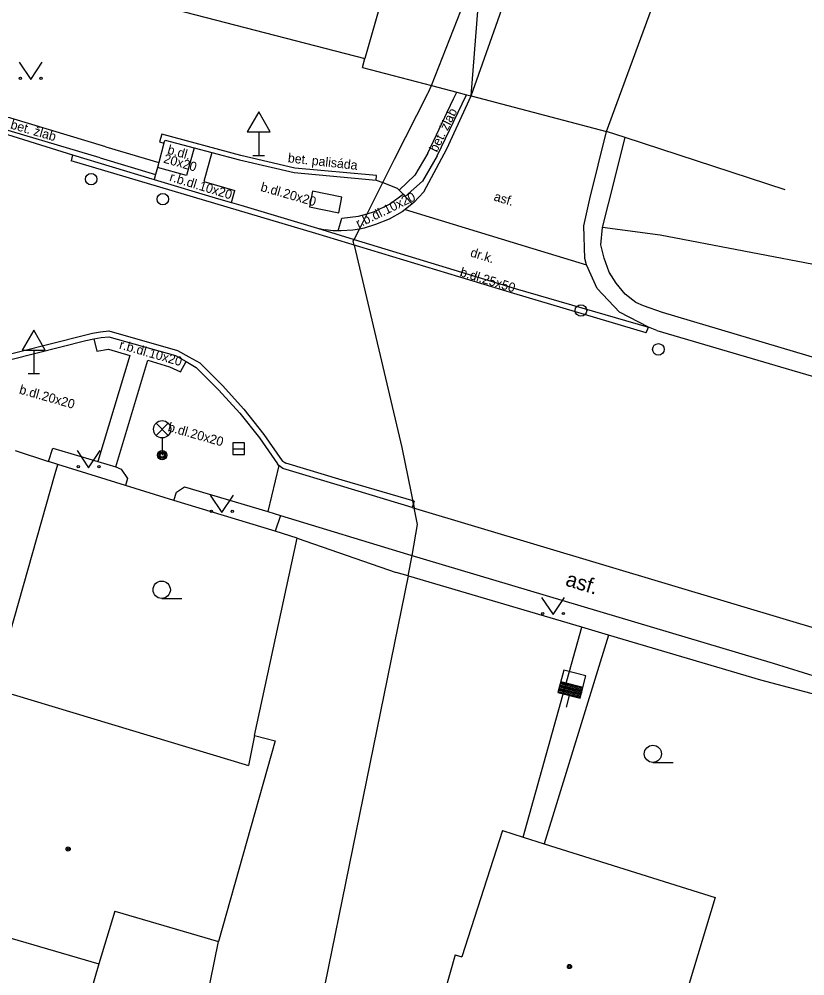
# Model space of a CAD drawing. Extents: x -599951 to -598963, y -1164095 to -1162939.
# Drawn here: x -599705.43 to -599671.33, y -1164061.65 to -1164020.14 of the extents above; entities that cross this region are included whole.
import ezdxf

# ---------------------------------------------------------------- set-up
doc = ezdxf.new("R2010")
doc.units = 0
for name, color, linetype in [('Level 1', 7, 'Continuous'), ('Level 10', 7, 'Continuous'), ('Level 11', 7, 'Continuous'), ('Level 14', 7, 'Continuous'), ('Level 26', 7, 'Continuous'), ('Level 27', 7, 'Continuous'), ('Level 28', 7, 'Continuous'), ('Level 33', 7, 'Continuous'), ('Level 34', 7, 'Continuous'), ('Level 36', 7, 'Continuous'), ('Level 39', 7, 'Continuous'), ('Level 40', 7, 'Continuous'), ('Level 42', 7, 'Continuous'), ('Level 5', 7, 'Continuous'), ('Level 7', 7, 'Continuous'), ('Level 8', 7, 'Continuous')]:
    doc.layers.add(name, color=color, linetype=linetype)

msp = doc.modelspace()

# ---------------------------------------------------------------- linework, layer by layer
at = {"layer": 'Level 1'}
for points in [[(-599689.65, -1164027.23), (-599689.14, -1164026.22), (-599687.7, -1164023.36), (-599687.67, -1164023.31), (-599687.53, -1164023.02), (-599685.47, -1164017.74), (-599684.35, -1164014.85), (-599680.77, -1164005.81)], [(-599689.65, -1164027.23), (-599689.14, -1164026.22), (-599687.7, -1164023.36), (-599687.67, -1164023.31), (-599687.53, -1164023.02), (-599685.47, -1164017.74), (-599684.35, -1164014.85), (-599680.77, -1164005.81)], [(-599690.33, -1164028.58), (-599689.65, -1164027.23)], [(-599690.66, -1164029.25), (-599690.33, -1164028.58)], [(-599690.66, -1164029.25), (-599690.33, -1164028.58)], [(-599690.89, -1164029.7), (-599690.66, -1164029.25)], [(-599690.89, -1164029.7), (-599690.66, -1164029.25)], [(-599690.89, -1164029.94), (-599690.93, -1164029.78), (-599690.89, -1164029.7)], [(-599690.89, -1164029.94), (-599690.93, -1164029.78), (-599690.89, -1164029.7)], [(-599690.89, -1164029.94), (-599688.82, -1164038.73), (-599688.29, -1164041.35)], [(-599690.89, -1164029.94), (-599688.82, -1164038.73), (-599688.29, -1164041.35)], [(-599688.32, -1164041.18), (-599688.35, -1164041.04)], [(-599688.54, -1164044.3), (-599688.37, -1164043.42), (-599688.14, -1164042.07), (-599688.29, -1164041.35)], [(-599688.54, -1164044.3), (-599688.37, -1164043.42), (-599688.14, -1164042.07), (-599688.29, -1164041.35)]]:
    msp.add_lwpolyline(points, dxfattribs=at)
at = {"layer": 'Level 10'}
for points in [[(-599679.94, -1164025.02), (-599673.88, -1164008.52), (-599673.11, -1164006.34)], [(-599737.46, -1164015.3), (-599717.42, -1164021.56), (-599703.11, -1164026.03)], [(-599686.87, -1164025.77), (-599685.82, -1164023.47)], [(-599680.67, -1164027.93), (-599679.94, -1164025.02)], [(-599703.11, -1164026.03), (-599699.67, -1164027.07), (-599699.57, -1164027.1), (-599696.78, -1164027.94), (-599696.21, -1164028.1), (-599695.81, -1164028.21), (-599692.48, -1164029.21)], [(-599687.86, -1164027.63), (-599686.87, -1164025.77)], [(-599687.86, -1164027.63), (-599688.3, -1164028.1), (-599688.37, -1164028.16), (-599688.67, -1164028.4), (-599688.81, -1164028.5), (-599689.37, -1164028.82), (-599689.97, -1164029.05)], [(-599680.93, -1164029.11), (-599680.67, -1164027.93)], [(-599689.97, -1164029.05), (-599690.45, -1164029.21), (-599690.66, -1164029.25)], [(-599692.48, -1164029.21), (-599692.14, -1164029.28)], [(-599691.45, -1164029.33), (-599691.59, -1164029.33), (-599691.8, -1164029.32), (-599692.14, -1164029.28)], [(-599690.66, -1164029.25), (-599690.95, -1164029.3), (-599691.45, -1164029.33)], [(-599690.66, -1164029.25), (-599690.95, -1164029.3), (-599691.45, -1164029.33)], [(-599680.34, -1164031.83), (-599680.81, -1164030.8), (-599680.88, -1164030.52), (-599680.93, -1164029.11)], [(-599679.38, -1164032.86), (-599680.34, -1164031.83)], [(-599677.76, -1164033.65), (-599678.12, -1164033.5), (-599679.38, -1164032.86)], [(-599702.53, -1164034.09), (-599702.18, -1164034.01), (-599701.87, -1164033.96), (-599701.54, -1164033.92)], [(-599701.54, -1164033.92), (-599698.64, -1164034.74), (-599698.18, -1164035), (-599697.74, -1164035.25)], [(-599677.76, -1164033.65), (-599663.13, -1164037.95), (-599638.89, -1164045.17)], [(-599706.89, -1164035.18), (-599702.53, -1164034.09)], [(-599697.74, -1164035.25), (-599696.77, -1164036.22), (-599695.85, -1164037.24), (-599695, -1164038.31), (-599694.22, -1164039.44)], [(-599688.37, -1164041.33), (-599691.48, -1164040.39), (-599693.98, -1164039.64), (-599694.16, -1164039.51), (-599694.22, -1164039.44)], [(-599688.37, -1164041.33), (-599671.86, -1164046.28)], [(-599688.37, -1164041.33), (-599671.86, -1164046.28)], [(-599671.86, -1164046.28), (-599639.5, -1164055.92), (-599621.28, -1164061.4)]]:
    msp.add_lwpolyline(points, dxfattribs=at)
at = {"layer": 'Level 11'}
for points in [[(-599701.67, -1164025.68), (-599735.28, -1164015.53), (-599734.93, -1164015.64), (-599737.84, -1164014.76), (-599764.73, -1164006.61), (-599764.17, -1164006.78), (-599768.63, -1164005.43), (-599780.82, -1164001.84), (-599795.4, -1163997.44), (-599802.23, -1163995.31), (-599807.23, -1163993.48), (-599810.52, -1163992.9), (-599813.08, -1163992.13), (-599851.66, -1163980.69), (-599860.84, -1163977.91), (-599859.39, -1163978.35), (-599896.02, -1163967.25), (-599909.01, -1163963.35), (-599920.55, -1163959.65), (-599941.4, -1163951.61), (-599950.74, -1163946.63), (-599950.31, -1163946.86), (-599951.125, -1163946.425)], [(-599685.82, -1164023.47), (-599679.21, -1164004.78)], [(-599685.82, -1164023.47), (-599685.42, -1164018.49), (-599685.47, -1164017.74), (-599685.51, -1164017.22), (-599685.74, -1164015.93), (-599686.51, -1164014.46)], [(-599685.82, -1164023.47), (-599685.42, -1164018.49), (-599685.47, -1164017.74), (-599685.51, -1164017.22), (-599685.74, -1164015.93), (-599686.51, -1164014.46)], [(-599701.91, -1164026.16), (-599717.42, -1164021.56)], [(-599690.53, -1164022.24), (-599690.42, -1164021.84)], [(-599687.7, -1164025.95), (-599686.58, -1164023.6), (-599686.44, -1164023.31), (-599686.01, -1164023.42)], [(-599687.29, -1164026.07), (-599686.01, -1164023.42)], [(-599689.92, -1164026.92), (-599693.46, -1164026.6), (-599695.81, -1164026.05), (-599699.24, -1164025.13), (-599699.34, -1164025.46)], [(-599677.51, -1164032.87), (-599678.33, -1164032.586), (-599678.671, -1164032.433), (-599679.135, -1164032.068), (-599679.529, -1164031.589), (-599679.824, -1164031.125), (-599680.049, -1164030.506), (-599680.182, -1164029.926), (-599680.115, -1164029.175), (-599679.856, -1164028.147), (-599679.13, -1164025.28)], [(-599701.67, -1164025.68), (-599699.36, -1164026.36)], [(-599699.15, -1164025.52), (-599699.36, -1164026.36), (-599699.42, -1164026.58), (-599699.51, -1164026.88), (-599699.57, -1164027.1)], [(-599697.83, -1164025.73), (-599698.16, -1164026.93)], [(-599703.11, -1164026.03), (-599703.17, -1164026.28)], [(-599697.06, -1164025.93), (-599697.41, -1164027.19)], [(-599687.7, -1164025.95), (-599688.25, -1164026.91), (-599688.94, -1164027.56)], [(-599687.29, -1164026.07), (-599687.93, -1164027.17), (-599688.67, -1164027.84)], [(-599678.22, -1164033.75), (-599683.96, -1164032.05), (-599692.55, -1164029.44), (-599703.17, -1164026.28)], [(-599678.22, -1164033.75), (-599683.96, -1164032.05), (-599692.55, -1164029.44), (-599703.17, -1164026.28)], [(-599701.91, -1164026.16), (-599699.51, -1164026.88)], [(-599698.16, -1164026.93), (-599699.42, -1164026.58)], [(-599697.41, -1164027.19), (-599696.06, -1164027.57)], [(-599689.94, -1164027.12), (-599689.65, -1164027.23)], [(-599689.65, -1164027.23), (-599689.03, -1164027.47), (-599688.94, -1164027.56), (-599688.76, -1164027.74), (-599688.67, -1164027.84), (-599688.37, -1164028.16)], [(-599689.65, -1164027.23), (-599689.03, -1164027.47), (-599688.94, -1164027.56), (-599688.76, -1164027.74), (-599688.67, -1164027.84), (-599688.37, -1164028.16)], [(-599696.21, -1164028.1), (-599696.06, -1164027.57)], [(-599690.33, -1164028.58), (-599690, -1164028.49), (-599689.35, -1164028.17), (-599688.76, -1164027.74)], [(-599690.33, -1164028.58), (-599690, -1164028.49), (-599689.35, -1164028.17), (-599688.76, -1164027.74)], [(-599691.42, -1164028.77), (-599690.7, -1164028.69), (-599690.33, -1164028.58)], [(-599688.67, -1164028.4), (-599683.47, -1164029.99)], [(-599691.59, -1164029.33), (-599691.42, -1164028.77)], [(-599692.48, -1164029.21), (-599690.89, -1164029.7)], [(-599690.89, -1164029.7), (-599683.9, -1164031.83)], [(-599690.89, -1164029.7), (-599683.9, -1164031.83)], [(-599683.47, -1164029.99), (-599680.81, -1164030.8)], [(-599683.9, -1164031.83), (-599678.12, -1164033.5)], [(-599596.35, -1164057.12), (-599617.6, -1164050.7), (-599625.85, -1164047.89), (-599634, -1164045.88), (-599638.54, -1164044.56), (-599660.54, -1164037.91), (-599660.28, -1164036.8), (-599661.4, -1164036.53), (-599661.73, -1164037.61), (-599663.03, -1164037.18), (-599677.51, -1164032.87)], [(-599678.22, -1164033.75), (-599678.12, -1164033.5)], [(-599706.9, -1164034.93), (-599702.59, -1164033.85)], [(-599702.59, -1164033.85), (-599702.24, -1164033.77), (-599701.89, -1164033.71), (-599701.54, -1164033.67)], [(-599702.18, -1164034.01), (-599702.06, -1164034.54), (-599701.55, -1164034.46), (-599700.62, -1164034.74), (-599702.01, -1164039.34)], [(-599701.54, -1164033.67), (-599698.55, -1164034.52), (-599698.06, -1164034.79), (-599697.59, -1164035.05)], [(-599701.23, -1164039.56), (-599699.84, -1164034.94), (-599698.9, -1164035.23), (-599698.42, -1164035.45), (-599698.18, -1164035)], [(-599697.59, -1164035.05), (-599696.6, -1164036.03), (-599695.67, -1164037.07), (-599694.81, -1164038.16), (-599694.01, -1164039.3)], [(-599704.15, -1164039.33), (-599703.96, -1164038.76)], [(-599703.96, -1164038.76), (-599702.01, -1164039.34)], [(-599703.96, -1164038.76), (-599702.01, -1164039.34)], [(-599702.01, -1164039.34), (-599701.23, -1164039.56), (-599701, -1164039.67), (-599700.73, -1164040.07), (-599700.81, -1164040.37)], [(-599702.01, -1164039.34), (-599701.23, -1164039.56), (-599701, -1164039.67), (-599700.73, -1164040.07), (-599700.81, -1164040.37)], [(-599694.01, -1164039.3), (-599693.98, -1164039.32), (-599693.86, -1164039.41)], [(-599688.29, -1164041.06), (-599691.41, -1164040.14), (-599693.86, -1164039.41)], [(-599688.29, -1164041.06), (-599691.41, -1164040.14), (-599693.86, -1164039.41)], [(-599706.51, -1164049.22), (-599706.02, -1164047.48), (-599703.858, -1164039.861), (-599703.74, -1164039.47)], [(-599694.16, -1164039.51), (-599694.63, -1164041.51)], [(-599698.71, -1164041.02), (-599698.6, -1164040.67)], [(-599698.71, -1164041.02), (-599698.6, -1164040.67)], [(-599698.6, -1164040.67), (-599698.25, -1164040.44)], [(-599698.6, -1164040.67), (-599698.25, -1164040.44)], [(-599698.25, -1164040.44), (-599694.63, -1164041.51), (-599694.09, -1164041.68)], [(-599698.25, -1164040.44), (-599694.63, -1164041.51), (-599694.09, -1164041.68)], [(-599688.29, -1164041.06), (-599688.37, -1164041.33)], [(-599688.29, -1164041.06), (-599688.37, -1164041.33)], [(-599694.09, -1164041.68), (-599694.32, -1164042.36)], [(-599694.09, -1164041.68), (-599688.57, -1164043.36), (-599672.71, -1164048.08)], [(-599694.09, -1164041.68), (-599688.57, -1164043.36), (-599672.71, -1164048.08)], [(-599695.21, -1164051.23), (-599693.36, -1164042.66)], [(-599688.54, -1164044.3), (-599694.72, -1164074.59)], [(-599688.54, -1164044.3), (-599694.72, -1164074.59)], [(-599683.56, -1164055.63), (-599681.01, -1164046.53)], [(-599679.85, -1164046.87), (-599682.65, -1164055.92)], [(-599672.71, -1164048.08), (-599670.11, -1164048.9), (-599667.74, -1164050.29)], [(-599701.21, -1164081.99), (-599696.77, -1164060.17)], [(-599701.97, -1164061.13), (-599703.51, -1164066.49)]]:
    msp.add_lwpolyline(points, dxfattribs=at)
at = {"layer": 'Level 14'}
msp.add_lwpolyline([(-599587.26, -1164049.45), (-599587.64, -1164047.53), (-599593, -1164047.51), (-599595.2, -1164048.95), (-599607.33, -1164046.09), (-599623.03, -1164041.85), (-599630.68, -1164039.44), (-599631.31, -1164034.32), (-599634.48, -1164028.79), (-599654.8, -1164024.23), (-599656.89, -1164030.03), (-599659.52, -1164029.78), (-599661.32, -1164033.38), (-599670.35, -1164030.9), (-599677.62, -1164029.52), (-599680.115, -1164029.175)], dxfattribs=at)
at = {"layer": 'Level 26'}
for points in [[(-599692.69, -1164027.61), (-599692.83, -1164028.28)], [(-599691.42, -1164027.87), (-599692.69, -1164027.61)], [(-599691.56, -1164028.54), (-599691.42, -1164027.87)], [(-599692.83, -1164028.28), (-599691.56, -1164028.54)]]:
    msp.add_lwpolyline(points, dxfattribs=at)
at = {"layer": 'Level 27'}
msp.add_line((-599696.15, -1164038.78), (-599695.65, -1164038.78), dxfattribs=at)
msp.add_lwpolyline([(-599696.15, -1164039.03), (-599695.65, -1164039.03), (-599695.65, -1164038.53), (-599696.15, -1164038.53)], close=True, dxfattribs=at)
at = {"layer": 'Level 28'}
for p, q in [((-599681.949, -1164048.972), (-599680.981, -1164049.222)), ((-599681.937, -1164048.923), (-599680.968, -1164049.173)), ((-599681.924, -1164048.875), (-599680.956, -1164049.125)), ((-599682.037, -1164049.311), (-599681.068, -1164049.561)), ((-599682.024, -1164049.262), (-599681.056, -1164049.512)), ((-599682.012, -1164049.214), (-599681.043, -1164049.464)), ((-599681.999, -1164049.165), (-599681.031, -1164049.415)), ((-599681.987, -1164049.117), (-599681.018, -1164049.367)), ((-599681.974, -1164049.069), (-599681.006, -1164049.319)), ((-599681.962, -1164049.02), (-599680.993, -1164049.27)), ((-599681.565, -1164049.484), (-599681.698, -1164049.997))]:
    msp.add_line(p, q, dxfattribs=at)
msp.add_lwpolyline([(-599682.049, -1164049.359), (-599681.081, -1164049.609), (-599680.831, -1164048.641), (-599681.799, -1164048.391)], close=True, dxfattribs=at)
for centre in [(-599702.3, -1164027.08), (-599699.19, -1164027.95), (-599681.05, -1164032.78), (-599677.69, -1164034.47)]:
    msp.add_circle(centre, 0.25, dxfattribs=at)
at = {"layer": 'Level 33'}
for p, q in [((-599699.485, -1164038.2), (-599698.955, -1164037.67)), ((-599699.485, -1164037.67), (-599698.955, -1164038.2)), ((-599699.22, -1164038.31), (-599699.22, -1164039.06))]:
    msp.add_line(p, q, dxfattribs=at)
for centre, radius in [((-599699.22, -1164037.935), 0.375), ((-599699.22, -1164039.06), 0.2), ((-599699.22, -1164039.06), 0.145), ((-599699.22, -1164039.06), 0.0876)]:
    msp.add_circle(centre, radius, dxfattribs=at)
at = {"layer": 'Level 34'}
for p, q in [((-599695.03, -1164025.032), (-599695.03, -1164026.05)), ((-599695.28, -1164026.05), (-599694.78, -1164026.05)), ((-599704.79, -1164034.502), (-599704.79, -1164035.52)), ((-599705.04, -1164035.52), (-599704.54, -1164035.52))]:
    msp.add_line(p, q, dxfattribs=at)
for points in [[(-599695.53, -1164025.032), (-599694.53, -1164025.032), (-599695.03, -1164024.166)], [(-599705.29, -1164034.502), (-599704.29, -1164034.502), (-599704.79, -1164033.636)]]:
    msp.add_lwpolyline(points, close=True, dxfattribs=at)
at = {"layer": 'Level 36'}
for p, q in [((-599699.24, -1164045.275), (-599698.365, -1164045.275)), ((-599677.93, -1164052.395), (-599677.055, -1164052.395))]:
    msp.add_line(p, q, dxfattribs=at)
for points in [[(-599705.42, -1164022.01), (-599704.92, -1164022.76), (-599704.42, -1164022.01)], [(-599702.91, -1164038.86), (-599702.41, -1164039.61), (-599701.91, -1164038.86)], [(-599697.13, -1164040.8), (-599696.63, -1164041.55), (-599696.13, -1164040.8)], [(-599682.76, -1164045.23), (-599682.26, -1164045.98), (-599681.76, -1164045.23)]]:
    msp.add_lwpolyline(points, dxfattribs=at)
for centre, radius in [((-599705.37, -1164022.71), 0.05), ((-599704.471, -1164022.71), 0.05), ((-599702.86, -1164039.56), 0.05), ((-599701.961, -1164039.56), 0.05), ((-599697.08, -1164041.5), 0.05), ((-599696.181, -1164041.5), 0.05), ((-599699.24, -1164044.9), 0.375), ((-599682.71, -1164045.93), 0.05), ((-599681.811, -1164045.93), 0.05), ((-599677.93, -1164052.02), 0.375)]:
    msp.add_circle(centre, radius, dxfattribs=at)
at = {"layer": 'Level 39'}
for centre, radius in [((-599703.3, -1164056.15), 0.09), ((-599703.3, -1164056.15), 0.0398), ((-599681.55, -1164061.25), 0.09), ((-599681.55, -1164061.25), 0.0398)]:
    msp.add_circle(centre, radius, dxfattribs=at)
at = {"layer": 'Level 5'}
for points in [[(-599688.22, -1164014.09), (-599690.42, -1164021.84)], [(-599718.09, -1164014.68), (-599690.42, -1164021.84)], [(-599706.51, -1164049.22), (-599705.69, -1164049.44), (-599695.48, -1164052.52)], [(-599694.32, -1164051.45), (-599696.77, -1164060.17)], [(-599695.21, -1164051.23), (-599695.48, -1164052.52)], [(-599695.21, -1164051.23), (-599694.32, -1164051.45)], [(-599684.45, -1164055.35), (-599686.22, -1164060.83)], [(-599684.45, -1164055.35), (-599683.56, -1164055.63), (-599682.65, -1164055.92), (-599675.23, -1164058.25)], [(-599675.23, -1164058.25), (-599678.24, -1164068.2)], [(-599710.54, -1164058.63), (-599701.97, -1164061.13)], [(-599701.28, -1164058.85), (-599701.97, -1164061.13)], [(-599701.28, -1164058.85), (-599696.77, -1164060.17)], [(-599686.51, -1164060.74), (-599687.87, -1164065.54), (-599688.13, -1164066.47)], [(-599686.51, -1164060.74), (-599686.22, -1164060.83)]]:
    msp.add_lwpolyline(points, dxfattribs=at)
at = {"layer": 'Level 7'}
for points in [[(-599690.53, -1164022.24), (-599687.53, -1164023.02), (-599686.44, -1164023.31), (-599686.01, -1164023.42), (-599685.82, -1164023.47)], [(-599690.53, -1164022.24), (-599687.53, -1164023.02), (-599686.44, -1164023.31), (-599686.01, -1164023.42), (-599685.82, -1164023.47)], [(-599672.19, -1164027.54), (-599679.13, -1164025.28), (-599679.94, -1164025.02)], [(-599699.34, -1164025.46), (-599699.15, -1164025.52)], [(-599699.15, -1164025.52), (-599699.09, -1164025.39), (-599697.83, -1164025.73), (-599697.06, -1164025.93), (-599695.86, -1164026.25), (-599693.49, -1164026.8), (-599689.94, -1164027.12), (-599689.92, -1164026.92)], [(-599694.32, -1164042.36), (-599698.71, -1164041.02), (-599700.81, -1164040.37), (-599703.74, -1164039.47), (-599704.15, -1164039.33)], [(-599673.25, -1164048.82), (-599679.85, -1164046.87), (-599681.01, -1164046.53), (-599688.52, -1164044.31), (-599688.54, -1164044.3), (-599689.06, -1164044.15)], [(-599673.25, -1164048.82), (-599679.85, -1164046.87), (-599681.01, -1164046.53), (-599688.52, -1164044.31), (-599688.54, -1164044.3), (-599689.06, -1164044.15)], [(-599667.74, -1164050.29), (-599673.25, -1164048.82)]]:
    msp.add_lwpolyline(points, dxfattribs=at)
at = {"layer": 'Level 8'}
for points in [[(-599685.82, -1164023.47), (-599679.94, -1164025.02)], [(-599705.6, -1164038.86), (-599704.15, -1164039.33)], [(-599693.36, -1164042.66), (-599694.32, -1164042.36)], [(-599693.36, -1164042.66), (-599689.06, -1164044.15)]]:
    msp.add_lwpolyline(points, dxfattribs=at)

# ---------------------------------------------------------------- texts
at = {"layer": 'Level 40'}
for s, height, rotation, p in [('b.dl.', 0.4, 344.1718, (-599699.02, -1164025.97)), ('20x20', 0.4, 344.1718, (-599699.19, -1164026.36)), ('r.b.dl.10x20', 0.4, 343, (-599698.93, -1164027.15)), ('b.dl.20x20', 0.4, 344.1718, (-599694.98, -1164027.59)), ('r.b.dl.10x20', 0.4, 26, (-599690.7, -1164029.21)), ('asf.', 0.4, 343, (-599684.86, -1164028)), ('dr.k.', 0.4, 343, (-599685.88, -1164030.43)), ('r.b.dl.10x20', 0.4, 344, (-599701.11, -1164034.43)), ('b.dl.20x20', 0.4, 344.1718, (-599705.45, -1164036.38)), ('b.dl.20x20', 0.4, 344.1718, (-599699, -1164038.01)), ('asf.', 0.65, 343.072, (-599681.76, -1164044.71))]:
    msp.add_text(s, height=height, rotation=rotation, dxfattribs=at).set_placement(p)
at = {"layer": 'Level 42'}
for s, rotation, p in [('bet. žlab', 63.7764, (-599687.3, -1164025.94)), ('bet. žlab', 343.9227, (-599705.83, -1164024.88)), ('bet. palisáda', 353.7561, (-599693.78, -1164026.35)), ('b.dl.25x50', 343, (-599686.33, -1164031.28))]:
    msp.add_text(s, height=0.4, rotation=rotation, dxfattribs=at).set_placement(p)

doc.saveas('drawing.dxf')
